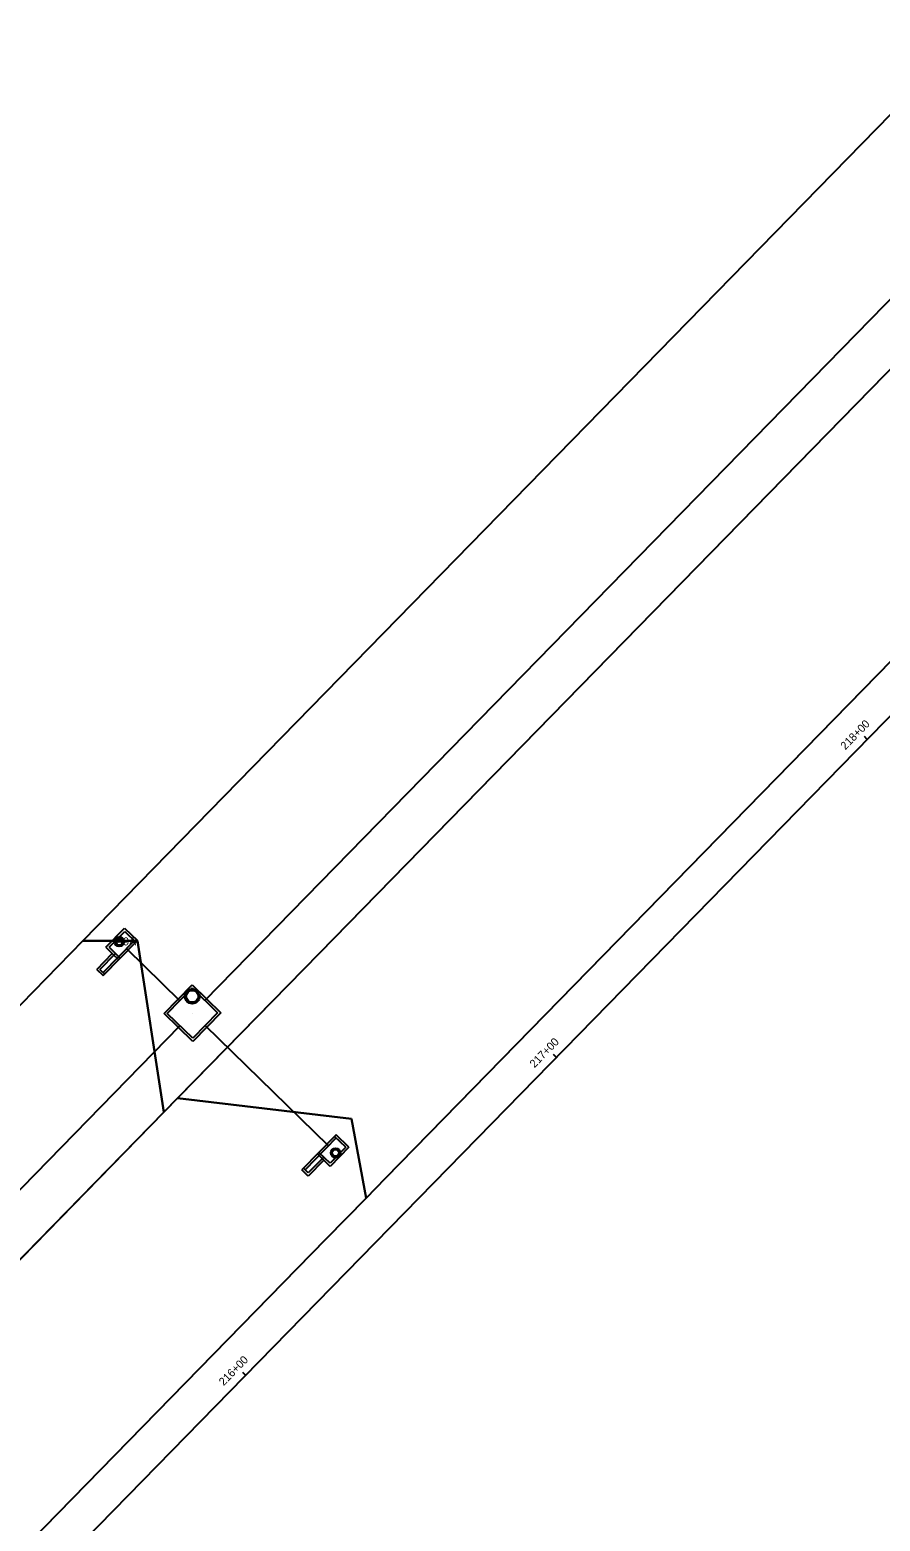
# Model space of a CAD drawing. Extents: x 2251012 to 2259557, y 13786786 to 13792525.
# Drawn here: x 2253773 to 2253964.2, y 13789549.7 to 13789885.2 of the extents above; entities that cross this region are included whole.
import ezdxf

# ---------------------------------------------------------------- set-up
doc = ezdxf.new("R2010")
doc.units = 0
for name, color, linetype in [('D_ALIGN_ANNO_1', 7, 'Continuous'), ('D_BOXES_1', 7, 'Continuous'), ('D_DRAIN_MISC', 7, 'Continuous'), ('D_DRAIN_NOTES_1', 7, 'Continuous'), ('D_DRN_AREA_A', 7, 'Continuous'), ('D_DRN_AREA_X', 7, 'Continuous'), ('D_INLET_1', 7, 'Continuous'), ('D_PIPES_1', 7, 'Continuous'), ('Grade_DitchLine', 7, 'Continuous')]:
    doc.layers.add(name, color=color, linetype=linetype)

msp = doc.modelspace()

# ---------------------------------------------------------------- linework, layer by layer
at = {"layer": 'D_ALIGN_ANNO_1'}
for p, q in [((2253961.3, 13789725.54), (2253960.66, 13789726.17)), ((2253891.41, 13789654.02), (2253890.77, 13789654.65)), ((2253821.52, 13789582.5), (2253820.87, 13789583.13))]:
    msp.add_line(p, q, dxfattribs=at)
at = {"layer": 'D_BOXES_1'}
for p, q in [((2253812.35, 13789666.84), (2253988.48, 13789847.07)), ((2253567.72, 13789416.52), (2253806.76, 13789661.12))]:
    msp.add_line(p, q, dxfattribs=at)
at = {"layer": 'D_DRAIN_MISC'}
for p, q in [((2253792.57, 13789680.58), (2253792.57, 13789680.58)), ((2253793.64, 13789679.53), (2253793.64, 13789679.53)), ((2253794.71, 13789678.48), (2253794.71, 13789678.48)), ((2253795.39, 13789681.32), (2253795.39, 13789681.32)), ((2253791.89, 13789677.74), (2253791.89, 13789677.74)), ((2253806.69, 13789666.77), (2253806.69, 13789666.77)), ((2253812.35, 13789666.84), (2253812.35, 13789666.84)), ((2253809.55, 13789663.98), (2253809.55, 13789663.98)), ((2253806.76, 13789661.12), (2253806.76, 13789661.12)), ((2253812.41, 13789661.18), (2253812.41, 13789661.18)), ((2253842.95, 13789634.84), (2253842.95, 13789634.84)), ((2253840.13, 13789634.1), (2253840.13, 13789634.1)), ((2253841.2, 13789633.05), (2253841.2, 13789633.05)), ((2253842.27, 13789632), (2253842.27, 13789632)), ((2253839.45, 13789631.26), (2253839.45, 13789631.26))]:
    msp.add_line(p, q, dxfattribs=at)
at = {"layer": 'D_DRN_AREA_A'}
for p, q in [((2253966.65, 13789866.22), (2253819.83, 13789715.98)), ((2253819.83, 13789715.98), (2253784.88, 13789680.23)), ((2253784.88, 13789680.23), (2253542.83, 13789432.54))]:
    msp.add_line(p, q, dxfattribs=at)
at = {"layer": 'D_DRN_AREA_X'}
for p, q in [((2254041.1, 13789885.17), (2253838.11, 13789677.46)), ((2253966.65, 13789866.22), (2253819.83, 13789715.98)), ((2253838.11, 13789677.46), (2253984.84, 13789827.6)), ((2253819.83, 13789715.98), (2253784.88, 13789680.23)), ((2253784.88, 13789680.23), (2253542.83, 13789432.54)), ((2253784.88, 13789680.23), (2253797.18, 13789680.26)), ((2253797.18, 13789680.26), (2253784.88, 13789680.23)), ((2253797.18, 13789680.26), (2253803.16, 13789641.7)), ((2253803.16, 13789641.7), (2253797.18, 13789680.26)), ((2253803.16, 13789641.7), (2253838.11, 13789677.46)), ((2253838.11, 13789677.46), (2253806.21, 13789644.82)), ((2253715.8, 13789552.3), (2253803.16, 13789641.7)), ((2253806.21, 13789644.82), (2253845.35, 13789640.18)), ((2253845.35, 13789640.18), (2253806.21, 13789644.82)), ((2253852.97, 13789626.85), (2253869.29, 13789643.54)), ((2253869.29, 13789643.54), (2253852.97, 13789626.85)), ((2253869.29, 13789643.54), (2253869.28, 13789643.54)), ((2253869.28, 13789643.54), (2253869.29, 13789643.54)), ((2253845.35, 13789640.18), (2253848.6, 13789622.38)), ((2253848.6, 13789622.38), (2253845.35, 13789640.18)), ((2253848.6, 13789622.38), (2253852.97, 13789626.85)), ((2253852.97, 13789626.85), (2253848.6, 13789622.38)), ((2253848.6, 13789622.38), (2253839.66, 13789613.23)), ((2253839.66, 13789613.23), (2253848.6, 13789622.38))]:
    msp.add_line(p, q, dxfattribs=at)
for points in [[(2254054.56, 13789833.13), (2253869.39, 13789643.66), (2253869.28, 13789643.54), (2253869.28, 13789643.54)], [(2253869.29, 13789643.54), (2253869.39, 13789643.65), (2254054.56, 13789833.13)], [(2253806.21, 13789644.82), (2253715.8, 13789552.3), (2253583.73, 13789417.16)], [(2253869.28, 13789643.54), (2253869.29, 13789643.54)], [(2253839.66, 13789613.23), (2253833.09, 13789606.51), (2253820.67, 13789593.8), (2253690.3, 13789460.4), (2253689.38, 13789459.45), (2253684.7, 13789454.66), (2253655.27, 13789424.55), (2253614.91, 13789383.25), (2253603.9, 13789371.99)], [(2253603.9, 13789371.99), (2253614.91, 13789383.25), (2253655.27, 13789424.55), (2253684.7, 13789454.66), (2253689.38, 13789459.45), (2253690.3, 13789460.4), (2253820.67, 13789593.8), (2253833.09, 13789606.51), (2253839.66, 13789613.23)]]:
    msp.add_lwpolyline(points, dxfattribs=at)
at = {"layer": 'D_INLET_1'}
for p, q in [((2253790.11, 13789678.78), (2253794.31, 13789683.07)), ((2253790.82, 13789678.79), (2253794.32, 13789682.37)), ((2253794.31, 13789683.07), (2253797.17, 13789680.28)), ((2253794.32, 13789682.37), (2253796.82, 13789679.92)), ((2253789.47, 13789673.12), (2253796.46, 13789680.27)), ((2253789.48, 13789672.41), (2253797.17, 13789680.28)), ((2253790.11, 13789678.78), (2253791.54, 13789677.38)), ((2253790.82, 13789678.79), (2253793.32, 13789676.34)), ((2253788.05, 13789673.81), (2253791.54, 13789677.38)), ((2253788.76, 13789673.82), (2253792.25, 13789677.39)), ((2253791.54, 13789677.38), (2253792.97, 13789675.99)), ((2253788.05, 13789673.81), (2253789.48, 13789672.41)), ((2253788.76, 13789673.82), (2253789.83, 13789672.77)), ((2253803.19, 13789663.9), (2253809.48, 13789670.34)), ((2253803.9, 13789663.91), (2253809.49, 13789669.63)), ((2253809.48, 13789670.34), (2253815.92, 13789664.05)), ((2253809.49, 13789669.63), (2253815.21, 13789664.04)), ((2253809.63, 13789657.61), (2253803.19, 13789663.9)), ((2253809.62, 13789658.32), (2253803.9, 13789663.91)), ((2253815.21, 13789664.04), (2253809.62, 13789658.32)), ((2253815.92, 13789664.05), (2253809.63, 13789657.61)), ((2253841.87, 13789636.59), (2253834.18, 13789628.73)), ((2253841.88, 13789635.89), (2253834.89, 13789628.73)), ((2253844.02, 13789633.79), (2253841.52, 13789636.24)), ((2253844.73, 13789633.8), (2253841.87, 13789636.59)), ((2253839.1, 13789631.61), (2253835.6, 13789628.04)), ((2253839.1, 13789630.9), (2253837.67, 13789632.3)), ((2253840.53, 13789630.21), (2253838.02, 13789632.66)), ((2253844.73, 13789633.8), (2253840.53, 13789629.51)), ((2253844.02, 13789633.79), (2253840.53, 13789630.21)), ((2253835.61, 13789627.33), (2253834.18, 13789628.73)), ((2253835.6, 13789628.04), (2253834.53, 13789629.08)), ((2253839.1, 13789630.9), (2253835.61, 13789627.33)), ((2253840.53, 13789629.51), (2253839.1, 13789630.9))]:
    msp.add_line(p, q, dxfattribs=at)
for centre, radius in [((2253793.1, 13789680.05), 1.08), ((2253793.1, 13789680.05), 0.75), ((2253809.51, 13789667.75), 1.67), ((2253809.51, 13789667.75), 1.33), ((2253841.74, 13789632.53), 1.08), ((2253841.74, 13789632.53), 0.75)]:
    msp.add_circle(centre, radius, dxfattribs=at)
at = {"layer": 'D_PIPES_1'}
for p, q in [((2253794.71, 13789678.48), (2253806.69, 13789666.77)), ((2253840.13, 13789634.1), (2253812.41, 13789661.18))]:
    msp.add_line(p, q, dxfattribs=at)
at = {"layer": 'Grade_DitchLine'}
msp.add_line((2253520.29, 13789274.27), (2254036.25, 13789802.23), dxfattribs=at)

# ---------------------------------------------------------------- texts
at = {"layer": 'D_ALIGN_ANNO_1'}
for s, p in [('218+00', (2253956.38, 13789723.08)), ('217+00', (2253886.48, 13789651.56)), ('216+00', (2253816.59, 13789580.04))]:
    msp.add_text(s, height=1.8, rotation=45.6588, dxfattribs=at).set_placement(p)
at = {"layer": 'D_DRAIN_NOTES_1'}
msp.add_text('A9A', height=1.8, dxfattribs=at).set_placement((2253792.37, 13789679.21))

doc.saveas('drawing.dxf')
